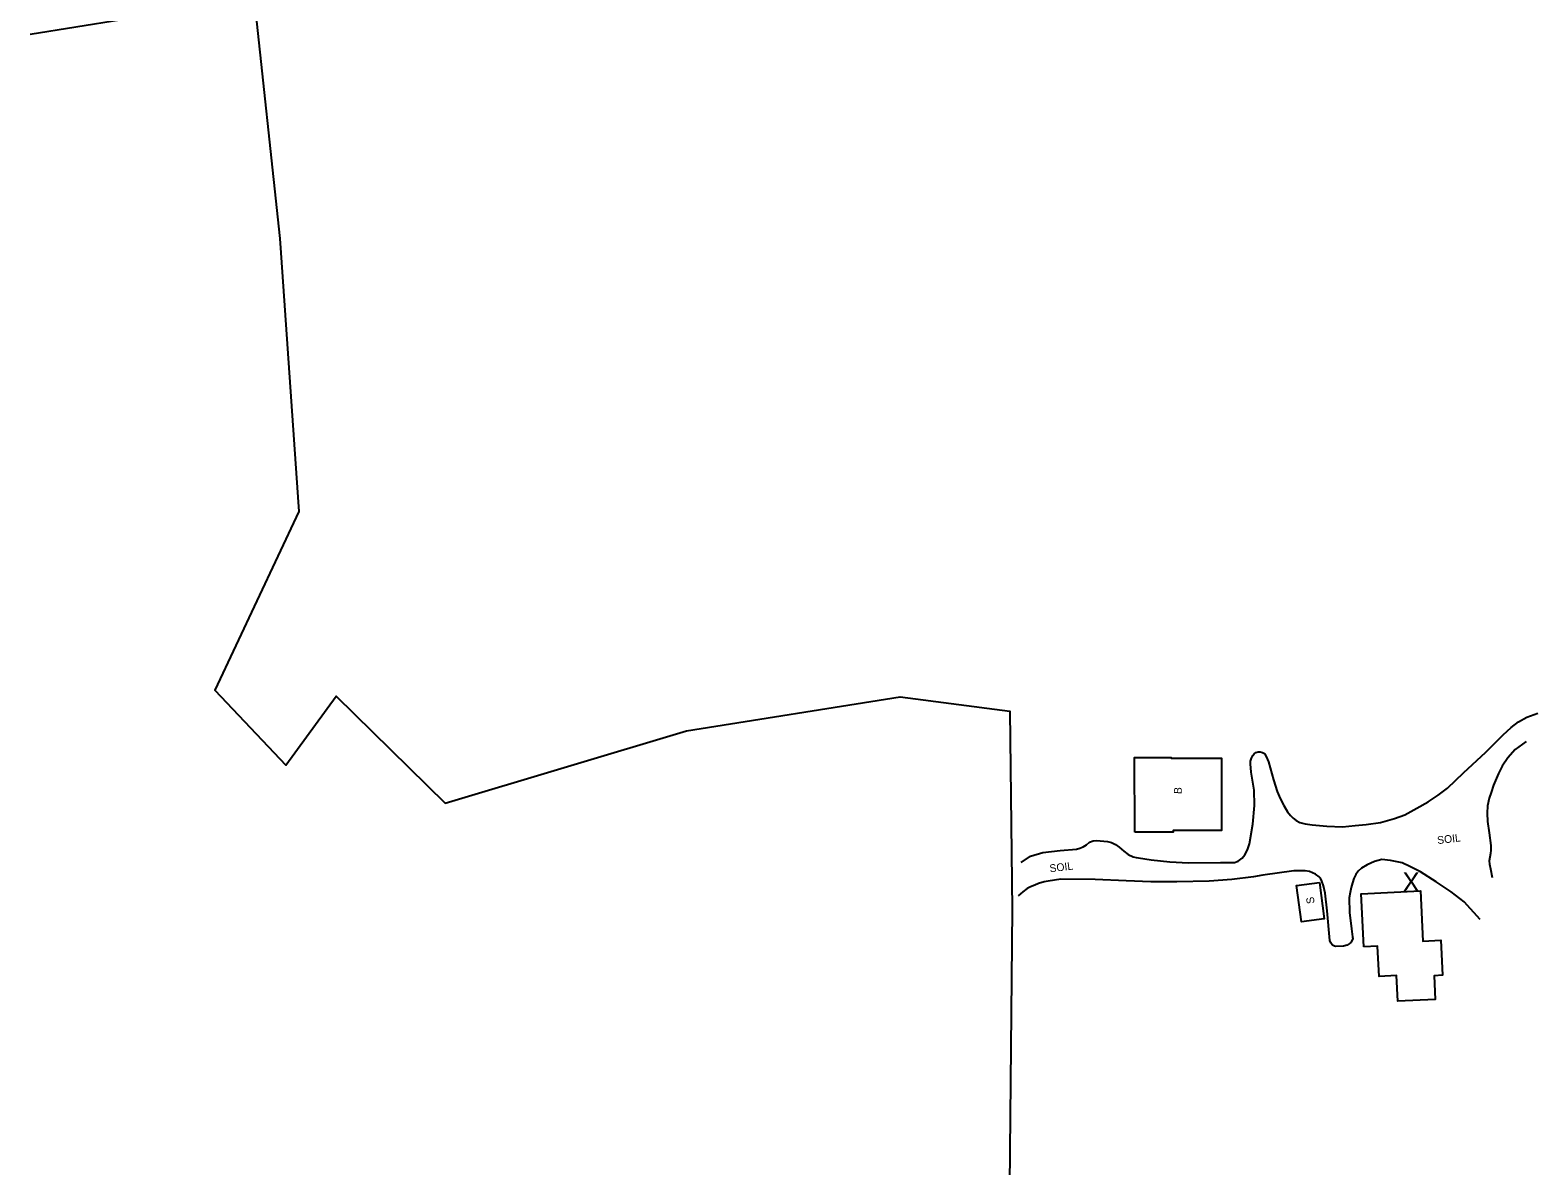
# Model space of a CAD drawing. Extents: x 2030130 to 2036320, y 723205 to 762423.
# Drawn here: x 2031992 to 2032771, y 730936 to 731523 of the extents above; entities that cross this region are included whole.
import ezdxf

# ---------------------------------------------------------------- set-up
doc = ezdxf.new("R2010")
doc.units = 0
for name, color, linetype in [('Draft_Station Labels Major', 7, 'Continuous'), ('Draft_Station Tics Major', 7, 'Continuous'), ('Exist Terrain Model Ground Surface', 7, 'Continuous'), ('Old_Level_23', 7, 'Continuous'), ('Old_Level_28', 7, 'Continuous')]:
    doc.layers.add(name, color=color, linetype=linetype)

msp = doc.modelspace()

# ---------------------------------------------------------------- linework, layer by layer
at = {"layer": 'Draft_Station Labels Major'}
for points in [[(2032503.98, 731092.52), (2032508.88, 731095.73), (2032515.25, 731097.6), (2032524.28, 731098.67), (2032532.66, 731099.45), (2032534.39, 731099.89), (2032536.12, 731100.61), (2032537.83, 731101.68), (2032539.45, 731102.92), (2032541.29, 731103.74), (2032543.06, 731103.9), (2032546.83, 731103.58), (2032548.7, 731103.36), (2032550.76, 731102.88), (2032552.84, 731101.76), (2032554.64, 731100.39), (2032557.08, 731098.41), (2032559.32, 731096.69), (2032561.91, 731095.43), (2032563.57, 731094.99), (2032564.77, 731094.84), (2032571.18, 731093.87), (2032580.93, 731092.78), (2032590.59, 731092.27), (2032607.1, 731092.52), (2032614.28, 731092.49), (2032616.14, 731093.17), (2032618.19, 731094.69), (2032619.6, 731096.41), (2032621.04, 731099.08), (2032622.1, 731102.14), (2032623.8, 731112.33), (2032624.64, 731121.96), (2032624.42, 731129.9), (2032622.87, 731139.14), (2032622.5, 731143.4), (2032622.59, 731144.82), (2032623.06, 731146.4), (2032623.74, 731147.72), (2032624.49, 731148.6), (2032625.31, 731149.25), (2032626.53, 731149.64), (2032627.51, 731149.68), (2032628.73, 731149.38), (2032629.71, 731148.74), (2032630.72, 731147.26), (2032631.86, 731144.43), (2032634.46, 731135.22), (2032636.41, 731129.1), (2032637.95, 731125.53), (2032639.75, 731121.87), (2032641.69, 731118.73), (2032643.3, 731116.72), (2032644.68, 731115.34), (2032646.17, 731114.13), (2032648.04, 731113.22), (2032650.86, 731112.5), (2032654.49, 731111.95), (2032661.96, 731111.28), (2032670.02, 731110.98), (2032676.67, 731111.52), (2032682.26, 731112.18), (2032689.76, 731113.23), (2032696.98, 731115.18), (2032702.22, 731117.19), (2032708.44, 731120.63), (2032714.31, 731123.82), (2032719.55, 731127.21), (2032724.42, 731130.98), (2032732.67, 731138.85), (2032744.13, 731149.54), (2032753.06, 731158.51), (2032757.16, 731162.24), (2032761.03, 731165.21), (2032765.42, 731167.62), (2032771.03, 731169.72)], [(2032765, 731155.03), (2032759.32, 731150.88), (2032755.55, 731146.64), (2032752.62, 731142.2), (2032750.73, 731138.49), (2032748.14, 731132.44), (2032746.85, 731128.62), (2032745.88, 731125.66), (2032744.99, 731121.79), (2032744.78, 731117.92), (2032745.02, 731113.7), (2032745.88, 731107.84), (2032746.77, 731101.22), (2032746.75, 731098.88), (2032746.55, 731097.07), (2032746.22, 731095.31), (2032745.92, 731093.39), (2032746.06, 731091.56), (2032746.52, 731089.21), (2032747.46, 731084.78)], [(2032741.29, 731063.02), (2032732.88, 731072.2), (2032726.23, 731077.39), (2032718.51, 731082.49), (2032710.36, 731087.72), (2032704.97, 731090.46), (2032700.95, 731092.23), (2032694.87, 731093.58), (2032690.5, 731094.01), (2032686.6, 731092.98), (2032682.91, 731091.26), (2032679.92, 731089.61), (2032678.27, 731088.04), (2032676.9, 731086.25), (2032675.93, 731084.19), (2032675.18, 731081.93), (2032674.51, 731079.51), (2032674.02, 731076.96), (2032673.51, 731074.15), (2032673.66, 731066.64), (2032674.67, 731058.12), (2032675.24, 731054.08), (2032675.35, 731053.28), (2032675.14, 731052.38), (2032674.44, 731051.21), (2032673.57, 731050.37), (2032672.48, 731049.73), (2032670.54, 731049.28), (2032666.6, 731049.03), (2032666.03, 731049.2), (2032664.95, 731049.73), (2032664.79, 731049.92), (2032664.08, 731050.96), (2032663.6, 731052.14), (2032662.24, 731067.48), (2032661.08, 731076.67), (2032660.3, 731080.49), (2032659.49, 731082.81), (2032658.71, 731084.36), (2032658.09, 731085.03), (2032656.12, 731086.53), (2032654.66, 731087.17), (2032652.97, 731087.76), (2032650.72, 731088.09), (2032645.03, 731088.22), (2032628.93, 731085.92), (2032624.17, 731085.01), (2032612.83, 731083.61), (2032601.26, 731082.82), (2032584.56, 731082.42), (2032571.1, 731082.42), (2032558.28, 731082.99), (2032542.35, 731083.74), (2032524.61, 731083.79), (2032517.98, 731082.89), (2032515.94, 731082.54), (2032513.04, 731081.62), (2032511.14, 731080.82), (2032508.95, 731079.96), (2032507.13, 731078.99), (2032504.9, 731077.32), (2032502.57, 731075.33)]]:
    msp.add_lwpolyline(points, dxfattribs=at)
at = {"layer": 'Draft_Station Tics Major'}
msp.add_lwpolyline([(2031992.02, 731520.63), (2032039.17, 731528.18), (2032077.3, 731540.1), (2032098.67, 731550.48), (2032106.29, 731546.74), (2032107.46, 731541.96), (2032121.07, 731414.97), (2032130.85, 731273.94), (2032087.39, 731181.47), (2032124.13, 731142.74), (2032150.1, 731178.37), (2032206.4, 731123.08), (2032331.16, 731160.56), (2032441.53, 731178.1), (2032498.26, 731170.73), (2032499.4, 731068.22), (2032497.75, 730889.92), (2032501.48, 730706.68)], dxfattribs=at)
at = {"layer": 'Exist Terrain Model Ground Surface'}
for points in [[(2032562.79, 731108.22), (2032562.64, 731146.7), (2032581.65, 731146.78), (2032581.65, 731146.37), (2032607.63, 731146.34), (2032607.58, 731108.97), (2032582.53, 731109.02), (2032582.53, 731108.2)], [(2032658.14, 731082.2), (2032660.68, 731063.32), (2032648.84, 731061.73), (2032646.3, 731080.6)], [(2032681.08, 731048.89), (2032679.75, 731076.35), (2032710.32, 731077.8), (2032711.54, 731051.88), (2032720.97, 731052.32), (2032721.83, 731034.19), (2032717.43, 731033.98), (2032718.02, 731021.74), (2032698.69, 731020.81), (2032698.05, 731034.08), (2032688.99, 731033.64), (2032688.25, 731049.3)]]:
    msp.add_lwpolyline(points, close=True, dxfattribs=at)

# ---------------------------------------------------------------- texts
at = {"layer": 'Draft_Station Tics Major'}
msp.add_text('X', height=10, dxfattribs=at).set_placement((2032701.07, 731077.42))
at = {"layer": 'Old_Level_23'}
for p in [(2032719.27, 731101.97), (2032518.97, 731087.41)]:
    msp.add_text('SOIL', height=4, rotation=6.79061, dxfattribs=at).set_placement(p)
at = {"layer": 'Old_Level_28'}
for s, rotation, p in [('B', 85.36463, (2032586.89, 731127.73)), ('S', 99.32787, (2032655.74, 731071.45))]:
    msp.add_text(s, height=4, rotation=rotation, dxfattribs=at).set_placement(p)

doc.saveas('drawing.dxf')
